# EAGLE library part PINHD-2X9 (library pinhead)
PIN HEADER
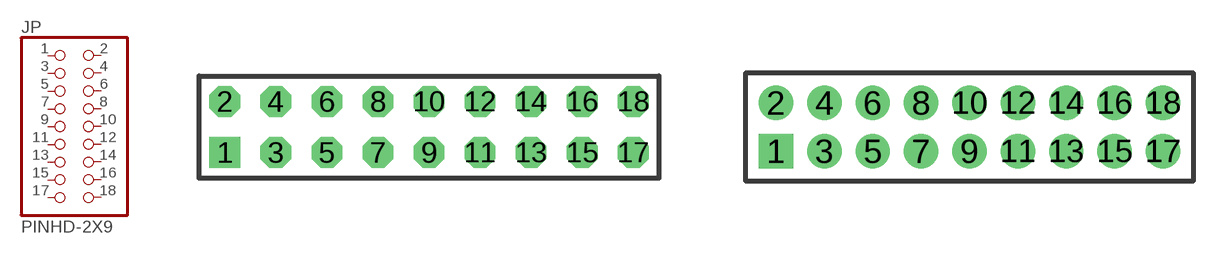
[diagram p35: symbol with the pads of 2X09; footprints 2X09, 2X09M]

Designator prefix JP

## PINHD-2X9  [2X09]
1  1  pas
2  2  pas
3  3  pas
4  4  pas
5  5  pas
6  6  pas
7  7  pas
8  8  pas
9  9  pas
10  10  pas
11  11  pas
12  12  pas
13  13  pas
14  14  pas
15  15  pas
16  16  pas
17  17  pas
18  18  pas

## PINHD-2X9M  [2X09M]
Pads as for 2X09

## Footprint 2X09 (pad centres in mm)
PIN HEADER - 0.1"
drill 1.016 square: 1 -10.16,-1.27
drill 1.016 octagon: 2 -10.16,1.27; 3 -7.62,-1.27; 4 -7.62,1.27; 5 -5.08,-1.27; 6 -5.08,1.27; 7 -2.54,-1.27; 8 -2.54,1.27; 9 0,-1.27; 10 0,1.27; 11 2.54,-1.27; 12 2.54,1.27; 13 5.08,-1.27; 14 5.08,1.27; 15 7.62,-1.27; 16 7.62,1.27; 17 10.16,-1.27; 18 10.16,1.27

## Footprint 2X09M (pad centres in mm)
PIN HEADER - 2MM"
drill 0.914 square: 1 -8,-1
drill 0.914 round: 2 -8,1; 3 -6,-1; 4 -6,1; 5 -4,-1; 6 -4,1; 7 -2,-1; 8 -2,1; 9 0,-1; 10 0,1; 11 2,-1; 12 2,1; 13 4,-1; 14 4,1; 15 6,-1; 16 6,1; 17 8,-1; 18 8,1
